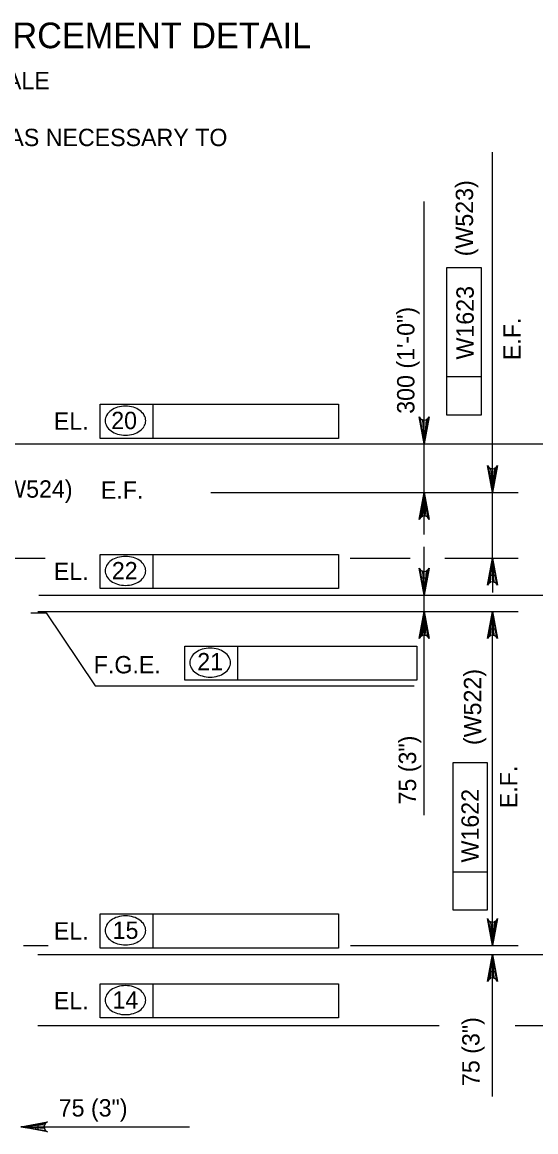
# Model space of a CAD drawing. Extents: x 638340 to 640241, y 295465 to 298435.
# Drawn here: x 639736.2 to 639825, y 297942.3 to 298134.1 of the extents above; entities that cross this region are included whole.
import ezdxf

# ---------------------------------------------------------------- set-up
doc = ezdxf.new("R2010")
doc.units = 0
doc.layers.add('3', color=7, linetype='Continuous')
doc.layers.add('4', color=7, linetype='Continuous')

msp = doc.modelspace()

# ---------------------------------------------------------------- linework, layer by layer
at = {"layer": '3'}
msp.add_line((639737.7, 298032.03), (639740.35, 298032.03), dxfattribs=at)
at = {"layer": '4'}
for p, q in [((639817.54, 298063.46), (639817.54, 298111.64)), ((639805.73, 298045.58), (639805.73, 298103.11)), ((639809.65, 298066.2), (639809.65, 298091.74)), ((639809.65, 298091.74), (639815.56, 298091.74)), ((639815.56, 298091.74), (639815.56, 298066.2)), ((639815.56, 298072.8), (639809.65, 298072.8)), ((639749.67, 298068.09), (639790.89, 298068.09)), ((639749.67, 298062.18), (639749.67, 298068.09)), ((639758.85, 298062.18), (639758.85, 298068.09)), ((639790.89, 298068.09), (639790.89, 298062.18)), ((639815.56, 298066.2), (639809.65, 298066.2)), ((639817.54, 298055.79), (639817.54, 298063.46)), ((639667.17, 298061.25), (639852.81, 298061.25)), ((639790.89, 298062.18), (639749.67, 298062.18)), ((639768.85, 298052.84), (639821.97, 298052.84)), ((639817.54, 298041.47), (639817.54, 298052.84)), ((639749.67, 298042.12), (639790.89, 298042.12)), ((639749.67, 298036.22), (639749.67, 298042.12)), ((639758.85, 298036.22), (639758.85, 298042.12)), ((639790.89, 298042.12), (639790.89, 298036.22)), ((639805.73, 297997.05), (639805.73, 298043.41)), ((639726.21, 298041.47), (639740.19, 298041.47)), ((639792.9, 298041.47), (639803.31, 298041.47)), ((639809.28, 298041.47), (639821.97, 298041.47)), ((639817.54, 298038.51), (639817.54, 298035.56)), ((639790.89, 298036.22), (639749.67, 298036.22)), ((639739.08, 298035.1), (639840.93, 298035.1)), ((639738.87, 298032.24), (639821.97, 298032.24)), ((639740.35, 298032.03), (639748.82, 298019.43)), ((639817.54, 297977.46), (639817.54, 298029.28)), ((639764.33, 298020.36), (639764.33, 298026.26)), ((639764.33, 298026.26), (639804.44, 298026.26)), ((639773.5, 298020.36), (639773.5, 298026.26)), ((639804.44, 298026.26), (639804.44, 298020.36)), ((639748.82, 298019.43), (639803.99, 298019.43)), ((639804.44, 298020.36), (639764.33, 298020.36)), ((639810.75, 297980.61), (639810.75, 298006.15)), ((639810.75, 298006.15), (639816.65, 298006.15)), ((639816.65, 298006.15), (639816.65, 297980.61)), ((639816.65, 297987.2), (639810.75, 297987.2)), ((639816.65, 297980.61), (639810.75, 297980.61)), ((639749.67, 297979.98), (639790.89, 297979.98)), ((639749.67, 297974.07), (639749.67, 297979.98)), ((639758.85, 297974.07), (639758.85, 297979.98)), ((639790.89, 297979.98), (639790.89, 297974.07)), ((639736.44, 297974.51), (639740.71, 297974.51)), ((639792.96, 297974.51), (639821.97, 297974.51)), ((639738.92, 297972.97), (639852.81, 297972.97)), ((639790.89, 297974.07), (639749.67, 297974.07)), ((639817.54, 297948.42), (639817.54, 297970.02)), ((639749.67, 297967.92), (639790.89, 297967.92)), ((639749.67, 297962.02), (639749.67, 297967.92)), ((639758.85, 297962.02), (639758.85, 297967.92)), ((639790.89, 297967.92), (639790.89, 297962.02)), ((639790.89, 297962.02), (639749.67, 297962.02)), ((639738.92, 297960.67), (639808.32, 297960.67)), ((639821.45, 297960.67), (639852.81, 297960.67)), ((639738.88, 297943.19), (639741.84, 297943.19)), ((639741.84, 297943.19), (639765.15, 297943.19))]:
    msp.add_line(p, q, dxfattribs=at)
for points in [[(639805.73, 298061.25), (639804.86, 298065.91), (639805.11, 298065.55), (639805.42, 298065.37), (639805.73, 298065.31), (639806.05, 298065.37), (639806.36, 298065.55), (639806.61, 298065.91), (639805.73, 298061.25), (639806.36, 298065.55), (639806.05, 298065.37), (639805.73, 298061.25), (639805.73, 298065.31), (639805.42, 298065.37), (639805.73, 298061.25), (639805.11, 298065.55)], [(639817.54, 298052.84), (639816.67, 298057.5), (639816.92, 298057.14), (639817.23, 298056.95), (639817.54, 298056.9), (639817.86, 298056.95), (639818.17, 298057.14), (639818.42, 298057.5), (639817.54, 298052.84), (639818.17, 298057.14), (639817.86, 298056.95), (639817.54, 298052.84), (639817.54, 298056.9), (639817.23, 298056.95), (639817.54, 298052.84), (639816.92, 298057.14)], [(639805.73, 298052.84), (639806.61, 298048.18), (639806.36, 298048.53), (639806.05, 298048.72), (639805.73, 298048.77), (639805.42, 298048.72), (639805.11, 298048.53), (639804.86, 298048.18), (639805.73, 298052.84), (639805.11, 298048.53), (639805.42, 298048.72), (639805.73, 298052.84), (639805.73, 298048.77), (639806.05, 298048.72), (639805.73, 298052.84), (639806.36, 298048.53)], [(639805.73, 298035.1), (639804.86, 298039.77), (639805.11, 298039.41), (639805.42, 298039.22), (639805.73, 298039.17), (639806.05, 298039.22), (639806.36, 298039.41), (639806.61, 298039.77), (639805.73, 298035.1), (639806.36, 298039.41), (639806.05, 298039.22), (639805.73, 298035.1), (639805.73, 298039.17), (639805.42, 298039.22), (639805.73, 298035.1), (639805.11, 298039.41)], [(639817.54, 298041.47), (639818.42, 298036.8), (639818.17, 298037.16), (639817.86, 298037.35), (639817.54, 298037.4), (639817.23, 298037.35), (639816.92, 298037.16), (639816.67, 298036.8), (639817.54, 298041.47), (639816.92, 298037.16), (639817.23, 298037.35), (639817.54, 298041.47), (639817.54, 298037.4), (639817.86, 298037.35), (639817.54, 298041.47), (639818.17, 298037.16)], [(639805.73, 298032.24), (639806.61, 298027.58), (639806.36, 298027.94), (639806.05, 298028.12), (639805.73, 298028.18), (639805.42, 298028.12), (639805.11, 298027.94), (639804.86, 298027.58), (639805.73, 298032.24), (639805.11, 298027.94), (639805.42, 298028.12), (639805.73, 298032.24), (639805.73, 298028.18), (639806.05, 298028.12), (639805.73, 298032.24), (639806.36, 298027.94)], [(639817.54, 298032.24), (639818.42, 298027.58), (639818.17, 298027.94), (639817.86, 298028.12), (639817.54, 298028.18), (639817.23, 298028.12), (639816.92, 298027.94), (639816.67, 298027.58), (639817.54, 298032.24), (639816.92, 298027.94), (639817.23, 298028.12), (639817.54, 298032.24), (639817.54, 298028.18), (639817.86, 298028.12), (639817.54, 298032.24), (639818.17, 298027.94)], [(639817.54, 297974.51), (639816.67, 297979.17), (639816.92, 297978.81), (639817.23, 297978.63), (639817.54, 297978.57), (639817.86, 297978.63), (639818.17, 297978.81), (639818.42, 297979.17), (639817.54, 297974.51), (639818.17, 297978.81), (639817.86, 297978.63), (639817.54, 297974.51), (639817.54, 297978.57), (639817.23, 297978.63), (639817.54, 297974.51), (639816.92, 297978.81)], [(639817.54, 297972.97), (639818.42, 297968.31), (639818.17, 297968.67), (639817.86, 297968.85), (639817.54, 297968.91), (639817.23, 297968.85), (639816.92, 297968.67), (639816.67, 297968.31), (639817.54, 297972.97), (639816.92, 297968.67), (639817.23, 297968.85), (639817.54, 297972.97), (639817.54, 297968.91), (639817.86, 297968.85), (639817.54, 297972.97), (639818.17, 297968.67)], [(639735.93, 297943.19), (639740.59, 297944.06), (639740.23, 297943.82), (639740.05, 297943.5), (639739.99, 297943.19), (639740.05, 297942.88), (639740.23, 297942.57), (639740.59, 297942.32), (639735.93, 297943.19), (639740.23, 297942.57), (639740.05, 297942.88), (639735.93, 297943.19), (639739.99, 297943.19), (639740.05, 297943.5), (639735.93, 297943.19), (639740.23, 297943.82)]]:
    msp.add_lwpolyline(points, dxfattribs=at)
for points in [[(639817.05, 298055.79), (639818.04, 298055.79), (639817.54, 298052.84)], [(639805.24, 298049.88), (639806.23, 298049.88), (639805.73, 298052.84)], [(639817.05, 298038.51), (639818.04, 298038.51), (639817.54, 298041.47)], [(639805.24, 298038.06), (639806.23, 298038.06), (639805.73, 298035.1)], [(639805.24, 298029.28), (639806.23, 298029.28), (639805.73, 298032.24)], [(639817.05, 298029.28), (639818.04, 298029.28), (639817.54, 298032.24)], [(639817.05, 297977.46), (639818.04, 297977.46), (639817.54, 297974.51)], [(639817.05, 297970.02), (639818.04, 297970.02), (639817.54, 297972.97)], [(639738.88, 297943.68), (639738.88, 297942.7), (639735.93, 297943.19)]]:
    msp.add_lwpolyline(points, close=True, dxfattribs=at)
for centre, radius, start, end in [((639753.18, 298064.77), 2.76, 125.6316, 149.9767), ((639753.71, 298064.04), 3.66, 106.5358, 125.6316), ((639754.05, 298062.88), 4.87, 90, 106.5358), ((639754.05, 298062.88), 4.87, 73.4642, 90), ((639754.4, 298064.04), 3.66, 54.3684, 73.4642), ((639754.92, 298064.77), 2.76, 30.0233, 54.3684), ((639752.38, 298065.24), 1.83, 149.9767, 180), ((639752.38, 298065.24), 1.83, 180, 210.0233), ((639755.73, 298065.24), 1.83, 0, 30.0233), ((639755.73, 298065.24), 1.83, 329.9767, 0), ((639753.18, 298065.7), 2.76, 210.0233, 234.3684), ((639753.71, 298066.44), 3.66, 234.3684, 253.4642), ((639754.05, 298067.6), 4.87, 253.4642, 270), ((639754.05, 298067.6), 4.87, 270, 286.5358), ((639754.4, 298066.44), 3.66, 286.5358, 305.6316), ((639754.92, 298065.7), 2.76, 305.6316, 329.9767), ((639753.71, 298038.08), 3.66, 106.5358, 125.6316), ((639754.05, 298036.91), 4.87, 90, 106.5358), ((639754.05, 298036.91), 4.87, 73.4642, 90), ((639754.4, 298038.08), 3.66, 54.3684, 73.4642), ((639752.38, 298039.28), 1.83, 149.9767, 180), ((639753.18, 298038.81), 2.76, 125.6316, 149.9767), ((639754.92, 298038.81), 2.76, 30.0233, 54.3684), ((639755.73, 298039.28), 1.83, 0, 30.0233), ((639752.38, 298039.28), 1.83, 180, 210.0233), ((639753.18, 298039.74), 2.76, 210.0233, 234.3684), ((639754.92, 298039.74), 2.76, 305.6316, 329.9767), ((639755.73, 298039.28), 1.83, 329.9767, 0), ((639753.71, 298040.48), 3.66, 234.3684, 253.4642), ((639754.05, 298041.64), 4.87, 253.4642, 270), ((639754.05, 298041.64), 4.87, 270, 286.5358), ((639754.4, 298040.48), 3.66, 286.5358, 305.6316), ((639767.03, 298023.42), 1.83, 149.9767, 180), ((639767.84, 298022.95), 2.76, 125.6316, 149.9767), ((639768.37, 298022.22), 3.66, 106.5358, 125.6316), ((639768.71, 298021.06), 4.87, 90, 106.5358), ((639768.71, 298021.06), 4.87, 73.4642, 90), ((639769.05, 298022.22), 3.66, 54.3684, 73.4642), ((639769.58, 298022.95), 2.76, 30.0233, 54.3684), ((639770.39, 298023.42), 1.83, 0, 30.0233), ((639767.03, 298023.42), 1.83, 180, 210.0233), ((639767.84, 298023.88), 2.76, 210.0233, 234.3684), ((639769.58, 298023.88), 2.76, 305.6316, 329.9767), ((639770.39, 298023.42), 1.83, 329.9767, 0), ((639768.37, 298024.62), 3.66, 234.3684, 253.4642), ((639768.71, 298025.78), 4.87, 253.4642, 270), ((639768.71, 298025.78), 4.87, 270, 286.5358), ((639769.05, 298024.62), 3.66, 286.5358, 305.6316), ((639753.18, 297976.67), 2.76, 125.6316, 149.9767), ((639753.71, 297975.93), 3.66, 106.5358, 125.6316), ((639754.05, 297974.77), 4.87, 90, 106.5358), ((639754.05, 297974.77), 4.87, 73.4642, 90), ((639754.4, 297975.93), 3.66, 54.3684, 73.4642), ((639754.92, 297976.67), 2.76, 30.0233, 54.3684), ((639752.38, 297977.13), 1.83, 149.9767, 180), ((639752.38, 297977.13), 1.83, 180, 210.0233), ((639755.73, 297977.13), 1.83, 0, 30.0233), ((639755.73, 297977.13), 1.83, 329.9767, 0), ((639753.18, 297977.6), 2.76, 210.0233, 234.3684), ((639753.71, 297978.33), 3.66, 234.3684, 253.4642), ((639754.05, 297979.49), 4.87, 253.4642, 270), ((639754.05, 297979.49), 4.87, 270, 286.5358), ((639754.4, 297978.33), 3.66, 286.5358, 305.6316), ((639754.92, 297977.6), 2.76, 305.6316, 329.9767), ((639753.18, 297964.61), 2.76, 125.6316, 149.9767), ((639753.71, 297963.88), 3.66, 106.5358, 125.6316), ((639754.05, 297962.72), 4.87, 90, 106.5358), ((639754.05, 297962.72), 4.87, 73.4642, 90), ((639754.4, 297963.88), 3.66, 54.3684, 73.4642), ((639754.92, 297964.61), 2.76, 30.0233, 54.3684), ((639752.38, 297965.08), 1.83, 149.9767, 180), ((639752.38, 297965.08), 1.83, 180, 210.0233), ((639755.73, 297965.08), 1.83, 0, 30.0233), ((639755.73, 297965.08), 1.83, 329.9767, 0), ((639753.18, 297965.54), 2.76, 210.0233, 234.3684), ((639753.71, 297966.28), 3.66, 234.3684, 253.4642), ((639754.4, 297966.28), 3.66, 286.5358, 305.6316), ((639754.92, 297965.54), 2.76, 305.6316, 329.9767), ((639754.05, 297967.44), 4.87, 253.4642, 270), ((639754.05, 297967.44), 4.87, 270, 286.5358)]:
    msp.add_arc(centre, radius, start, end, dxfattribs=at)

# ---------------------------------------------------------------- texts
for s, height, p in [('WEEPHOLE REINFORCEMENT DETAIL', 4.4294, (639676.91, 298129.62)), ('NO SCALE', 3, (639720.67, 298122.53)), ('ADJUST REINFORCEMENT AS NECESSARY TO', 3.0001, (639680.97, 298112.7)), ('EL.', 3, (639741.66, 298063.66)), ('20', 3, (639751.59, 298063.78)), ('(W524)', 3, (639731.75, 298051.93)), ('E.F.', 3, (639749.8, 298051.74)), ('EL.', 3, (639741.66, 298037.7)), ('22', 3, (639751.7, 298037.81)), ('F.G.E.', 3, (639748.57, 298021.56)), ('21', 3, (639766.47, 298022.08)), ('EL.', 3, (639741.66, 297975.55)), ('15', 3, (639751.84, 297975.67)), ('EL.', 3, (639741.66, 297963.5)), ('14', 3, (639751.81, 297963.62)), ('75 (3")', 3, (639742.51, 297944.96))]:
    msp.add_text(s, height=height, dxfattribs=at).set_placement(p)
for s, height, p in [('(W523)', 3, (639814.19, 298093.65)), ('W1623', 3, (639814.3, 298075.81)), ('300 (1\'-0")', 3.0001, (639804.04, 298066.43)), ('E.F.', 3, (639822.42, 298075.7)), ('(W522)', 3, (639815.6, 298009.17)), ('75 (3")', 3, (639804.34, 297998.9)), ('E.F.', 3, (639821.82, 297998.25)), ('W1622', 3, (639815.17, 297988.87)), ('75 (3")', 3, (639815.31, 297950.23))]:
    msp.add_text(s, height=height, rotation=90, dxfattribs=at).set_placement(p)

doc.saveas('drawing.dxf')
